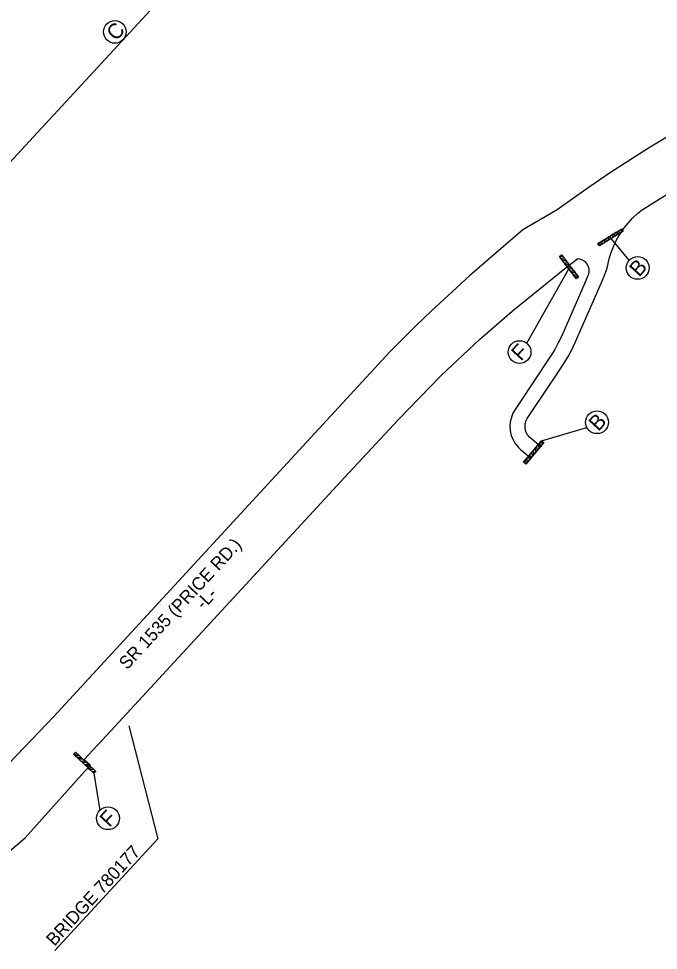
# Model space of a CAD drawing. Extents: x 1767460 to 1770129, y 996106 to 1001438.
# Drawn here: x 1768857 to 1769280, y 1000015 to 1000630 of the extents above; entities that cross this region are included whole.
import ezdxf

# ---------------------------------------------------------------- set-up
doc = ezdxf.new("R2010")
doc.units = 0
for name, color, linetype in [('_CIVIL_CONSTRUCTION', 7, 'Continuous'), ('E_NCDOT_Terrain_Model_Contour_Major', 7, 'Continuous'), ('E_NCDOT_Terrain_Model_Flow_Arrows', 7, 'Continuous'), ('E_NCDOT_Terrain_Model_Spot_Elevation', 7, 'Continuous'), ('E_NCDOT_Terrain_Model_Triangles', 7, 'Continuous'), ('P_NCDOT_Terrain_Void', 7, 'Continuous')]:
    doc.layers.add(name, color=color, linetype=linetype)

msp = doc.modelspace()

# ---------------------------------------------------------------- linework, layer by layer
at = {"layer": '_CIVIL_CONSTRUCTION'}
for centre in [(1768920.99, 1000621.59), (1769266.76, 1000465.6), (1769188.68, 1000410.01), (1769239.87, 1000363.59), (1768916.5, 1000101.92)]:
    msp.add_circle(centre, 7.5, dxfattribs=at)
at = {"layer": 'E_NCDOT_Terrain_Model_Contour_Major'}
for points in [[(1769296.01, 1000557.91), (1769273.97, 1000544.69), (1769259.2, 1000535.36), (1769248.9, 1000528.61), (1769235.29, 1000519.4), (1769226.59, 1000513.33), (1769213.58, 1000503.97), (1769190.81, 1000490.79), (1769155.62, 1000460.47), (1769130.16, 1000437.1), (1769120.02, 1000427.3), (1769102.92, 1000410.06), (1769050.61, 1000353.51), (1768880.7, 1000169.1), (1768831.33, 1000117.91)], [(1768828.95, 1000061.29), (1768861.74, 1000088.93), (1768901.22, 1000133.11), (1768904.88, 1000137.07), (1768900.84, 1000140.8), (1768918.39, 1000159.79), (1769075.87, 1000330.16), (1769108.52, 1000365.47), (1769136.89, 1000394.48), (1769162.15, 1000418.24), (1769183.68, 1000437.09), (1769219.6, 1000466.01), (1769227.18, 1000471.76), (1769228.51, 1000471.55), (1769230.84, 1000470.55), (1769231.54, 1000470.06), (1769233, 1000468.56), (1769233.88, 1000467.07), (1769234.44, 1000465.27), (1769234.56, 1000463.12), (1769234.2, 1000461.34), (1769233.44, 1000459.49), (1769231.96, 1000456.12), (1769221.61, 1000432.45), (1769216.51, 1000420.8), (1769214.29, 1000416.08), (1769211.88, 1000411.6), (1769210.05, 1000408.54), (1769205.67, 1000401.91), (1769201.42, 1000395.56), (1769185.65, 1000371.98), (1769184.29, 1000369.6), (1769183.47, 1000367.68), (1769183, 1000366.21), (1769182.47, 1000363.61), (1769182.28, 1000360.92), (1769182.42, 1000358.47), (1769182.67, 1000356.92), (1769183.2, 1000354.85), (1769184.11, 1000352.5), (1769184.84, 1000351.07), (1769185.64, 1000349.76), (1769186.97, 1000347.99), (1769187.9, 1000346.95), (1769189.39, 1000345.57), (1769191.76, 1000343.57), (1769196.14, 1000339.87), (1769202.59, 1000347.52), (1769196.86, 1000352.35), (1769195.42, 1000353.58), (1769193.99, 1000355.26), (1769193.12, 1000356.84), (1769192.42, 1000359.2), (1769192.28, 1000360.7), (1769192.44, 1000362.69), (1769193.06, 1000364.73), (1769193.76, 1000366.11), (1769207.59, 1000386.79), (1769212.63, 1000394.33), (1769215.15, 1000398.1), (1769218.4, 1000403.04), (1769220.82, 1000407.09), (1769222.95, 1000411.05), (1769225.67, 1000416.79), (1769227.73, 1000421.49), (1769236.65, 1000441.87), (1769243.45, 1000457.43), (1769244.66, 1000460.19), (1769246.14, 1000464.06), (1769246.96, 1000467.33), (1769247.47, 1000469.74), (1769248.19, 1000472.53), (1769249.46, 1000476.51), (1769250.94, 1000480.22), (1769252.21, 1000482.92), (1769253.46, 1000485.3), (1769257.3, 1000491.34), (1769259.05, 1000493.64), (1769263.32, 1000498.42), (1769266.98, 1000501.82), (1769269.74, 1000504.03), (1769303.4, 1000525.13)]]:
    msp.add_lwpolyline(points, dxfattribs=at)
at = {"layer": 'E_NCDOT_Terrain_Model_Flow_Arrows'}
for p, q in [((1769261.25, 1000470.69), (1769249.31, 1000485.15)), ((1769193.4, 1000415.84), (1769221.3, 1000465.04)), ((1769203.27, 1000351.33), (1769233.2, 1000360.15)), ((1768907.11, 1000131.61), (1768910.99, 1000107.01))]:
    msp.add_line(p, q, dxfattribs=at)
at = {"layer": 'E_NCDOT_Terrain_Model_Spot_Elevation'}
for p, q in [((1769240.48, 1000481.86), (1769256.24, 1000491.54)), ((1769257.19, 1000489.98), (1769241.44, 1000480.31)), ((1769251.37, 1000486.38), (1769251.98, 1000488.92)), ((1769251.98, 1000488.92), (1769253.4, 1000489.79)), ((1769253.4, 1000489.79), (1769252.79, 1000487.25)), ((1769254.21, 1000488.12), (1769254.82, 1000490.66)), ((1769255.63, 1000488.99), (1769254.21, 1000488.12)), ((1769254.82, 1000490.66), (1769256.24, 1000491.54)), ((1769256.24, 1000491.54), (1769255.63, 1000488.99)), ((1769256.24, 1000491.54), (1769257.19, 1000489.98)), ((1769240.48, 1000481.86), (1769242.03, 1000482.81)), ((1769242.03, 1000482.81), (1769241.45, 1000480.28)), ((1769242.87, 1000481.15), (1769243.45, 1000483.68)), ((1769243.45, 1000483.68), (1769244.87, 1000484.55)), ((1769244.87, 1000484.55), (1769244.29, 1000482.02)), ((1769245.7, 1000482.89), (1769246.29, 1000485.43)), ((1769247.12, 1000483.77), (1769245.7, 1000482.89)), ((1769246.29, 1000485.43), (1769247.7, 1000486.3)), ((1769247.7, 1000486.3), (1769247.12, 1000483.77)), ((1769248.54, 1000484.64), (1769249.12, 1000487.17)), ((1769249.96, 1000485.51), (1769248.54, 1000484.64)), ((1769249.12, 1000487.17), (1769250.54, 1000488.04)), ((1769250.54, 1000488.04), (1769249.96, 1000485.51)), ((1769252.79, 1000487.25), (1769251.37, 1000486.38)), ((1769241.45, 1000480.28), (1769240.48, 1000481.86)), ((1769241.44, 1000480.31), (1769240.48, 1000481.86)), ((1769244.29, 1000482.02), (1769242.87, 1000481.15)), ((1769215.01, 1000473.15), (1769216.48, 1000474.27)), ((1769217.58, 1000472.83), (1769215.01, 1000473.15)), ((1769215.03, 1000473.17), (1769216.48, 1000474.27)), ((1769226.25, 1000458.47), (1769215.03, 1000473.17)), ((1769216.01, 1000471.83), (1769218.59, 1000471.5)), ((1769217.02, 1000470.5), (1769216.01, 1000471.83)), ((1769216.48, 1000474.27), (1769217.58, 1000472.83)), ((1769216.48, 1000474.27), (1769227.69, 1000459.58)), ((1769219.6, 1000470.18), (1769217.02, 1000470.5)), ((1769218.59, 1000471.5), (1769219.6, 1000470.18)), ((1769218.03, 1000469.18), (1769220.61, 1000468.86)), ((1769219.04, 1000467.86), (1769218.03, 1000469.18)), ((1769221.62, 1000467.54), (1769219.04, 1000467.86)), ((1769220.05, 1000466.54), (1769222.63, 1000466.21)), ((1769221.06, 1000465.22), (1769220.05, 1000466.54)), ((1769220.61, 1000468.86), (1769221.62, 1000467.54)), ((1769223.64, 1000464.89), (1769221.06, 1000465.22)), ((1769222.63, 1000466.21), (1769223.64, 1000464.89)), ((1769222.07, 1000463.89), (1769224.67, 1000463.54)), ((1769223.08, 1000462.57), (1769222.07, 1000463.89)), ((1769225.68, 1000462.22), (1769223.08, 1000462.57)), ((1769224.09, 1000461.25), (1769226.68, 1000460.9)), ((1769225.1, 1000459.93), (1769224.09, 1000461.25)), ((1769224.67, 1000463.54), (1769225.68, 1000462.22)), ((1769227.69, 1000459.58), (1769225.1, 1000459.93)), ((1769227.69, 1000459.58), (1769226.25, 1000458.47)), ((1769226.68, 1000460.9), (1769227.69, 1000459.58)), ((1769191.36, 1000337.2), (1769203.27, 1000351.33)), ((1769204.66, 1000350.16), (1769192.75, 1000336.02)), ((1769200.05, 1000347.52), (1769201.13, 1000348.79)), ((1769200.28, 1000344.91), (1769200.05, 1000347.52)), ((1769201.13, 1000348.79), (1769201.35, 1000346.18)), ((1769202.2, 1000350.06), (1769203.27, 1000351.33)), ((1769202.42, 1000347.45), (1769202.2, 1000350.06)), ((1769203.49, 1000348.72), (1769202.42, 1000347.45)), ((1769203.27, 1000351.33), (1769203.49, 1000348.72)), ((1769203.27, 1000351.33), (1769204.66, 1000350.16)), ((1769193.6, 1000339.86), (1769194.67, 1000341.13)), ((1769194.67, 1000341.13), (1769194.92, 1000338.55)), ((1769195.74, 1000342.4), (1769196.82, 1000343.68)), ((1769195.99, 1000339.82), (1769195.74, 1000342.4)), ((1769197.06, 1000341.09), (1769195.99, 1000339.82)), ((1769196.82, 1000343.68), (1769197.06, 1000341.09)), ((1769197.89, 1000344.95), (1769198.96, 1000346.22)), ((1769198.13, 1000342.36), (1769197.89, 1000344.95)), ((1769199.2, 1000343.63), (1769198.13, 1000342.36)), ((1769198.96, 1000346.22), (1769199.2, 1000343.63)), ((1769201.35, 1000346.18), (1769200.28, 1000344.91)), ((1769191.36, 1000337.2), (1769192.53, 1000338.59)), ((1769192.77, 1000336), (1769191.36, 1000337.2)), ((1769192.75, 1000336.02), (1769191.36, 1000337.2)), ((1769192.53, 1000338.59), (1769192.77, 1000336)), ((1769193.84, 1000337.28), (1769193.6, 1000339.86)), ((1769194.92, 1000338.55), (1769193.84, 1000337.28)), ((1768893.71, 1000144.35), (1768894.97, 1000145.67)), ((1768893.71, 1000144.35), (1768896.33, 1000144.41)), ((1768894.92, 1000143.2), (1768893.71, 1000144.35)), ((1768907.11, 1000131.61), (1768893.71, 1000144.35)), ((1768894.97, 1000145.67), (1768908.37, 1000132.93)), ((1768896.33, 1000144.41), (1768897.54, 1000143.27)), ((1768897.54, 1000143.27), (1768894.92, 1000143.2)), ((1768896.13, 1000142.06), (1768898.74, 1000142.12)), ((1768897.33, 1000140.91), (1768896.13, 1000142.06)), ((1768899.95, 1000140.98), (1768897.33, 1000140.91)), ((1768898.56, 1000139.74), (1768901.15, 1000139.83)), ((1768899.77, 1000138.6), (1768898.56, 1000139.74)), ((1768898.74, 1000142.12), (1768899.95, 1000140.98)), ((1768902.36, 1000138.69), (1768899.77, 1000138.6)), ((1768901.15, 1000139.83), (1768902.36, 1000138.69)), ((1768900.97, 1000137.45), (1768903.57, 1000137.54)), ((1768902.18, 1000136.31), (1768900.97, 1000137.45)), ((1768904.77, 1000136.39), (1768902.18, 1000136.31)), ((1768903.38, 1000135.16), (1768905.98, 1000135.25)), ((1768904.59, 1000134.01), (1768903.38, 1000135.16)), ((1768903.57, 1000137.54), (1768904.77, 1000136.39)), ((1768907.18, 1000134.1), (1768904.59, 1000134.01)), ((1768905.79, 1000132.87), (1768908.39, 1000132.96)), ((1768907.11, 1000131.61), (1768905.79, 1000132.87)), ((1768905.98, 1000135.25), (1768907.18, 1000134.1)), ((1768908.39, 1000132.96), (1768907.11, 1000131.61)), ((1768908.37, 1000132.93), (1768907.11, 1000131.61))]:
    msp.add_line(p, q, dxfattribs=at)
at = {"layer": 'E_NCDOT_Terrain_Model_Triangles'}
for p in [(1768930.38, 1000163.07), (1768881.28, 1000014.62)]:
    msp.add_line(p, (1768949.44, 1000088.36), dxfattribs=at)
at = {"layer": 'P_NCDOT_Terrain_Void'}
msp.add_line((1768653.55, 1000321.21), (1769189.14, 1000900.63), dxfattribs=at)

# ---------------------------------------------------------------- texts
at = {"layer": '_CIVIL_CONSTRUCTION'}
for s, p in [('C', (1768921.82, 1000615.12)), ('B', (1769267.63, 1000459.18)), ('F', (1769189.57, 1000403.61)), ('B', (1769240.75, 1000357.17)), ('F', (1768917.39, 1000095.52))]:
    msp.add_text(s, height=10, rotation=47.25123, dxfattribs=at).set_placement(p)
at = {"layer": 'E_NCDOT_Terrain_Model_Triangles'}
for s, p in [('SR 1535 (PRICE RD.)', (1768929.11, 1000199.59)), ('-L-', (1768979.81, 1000239.4)), ('BRIDGE 780177', (1768881.03, 1000016.94))]:
    msp.add_text(s, height=8.5, rotation=47.25123, dxfattribs=at).set_placement(p)

doc.saveas('drawing.dxf')
